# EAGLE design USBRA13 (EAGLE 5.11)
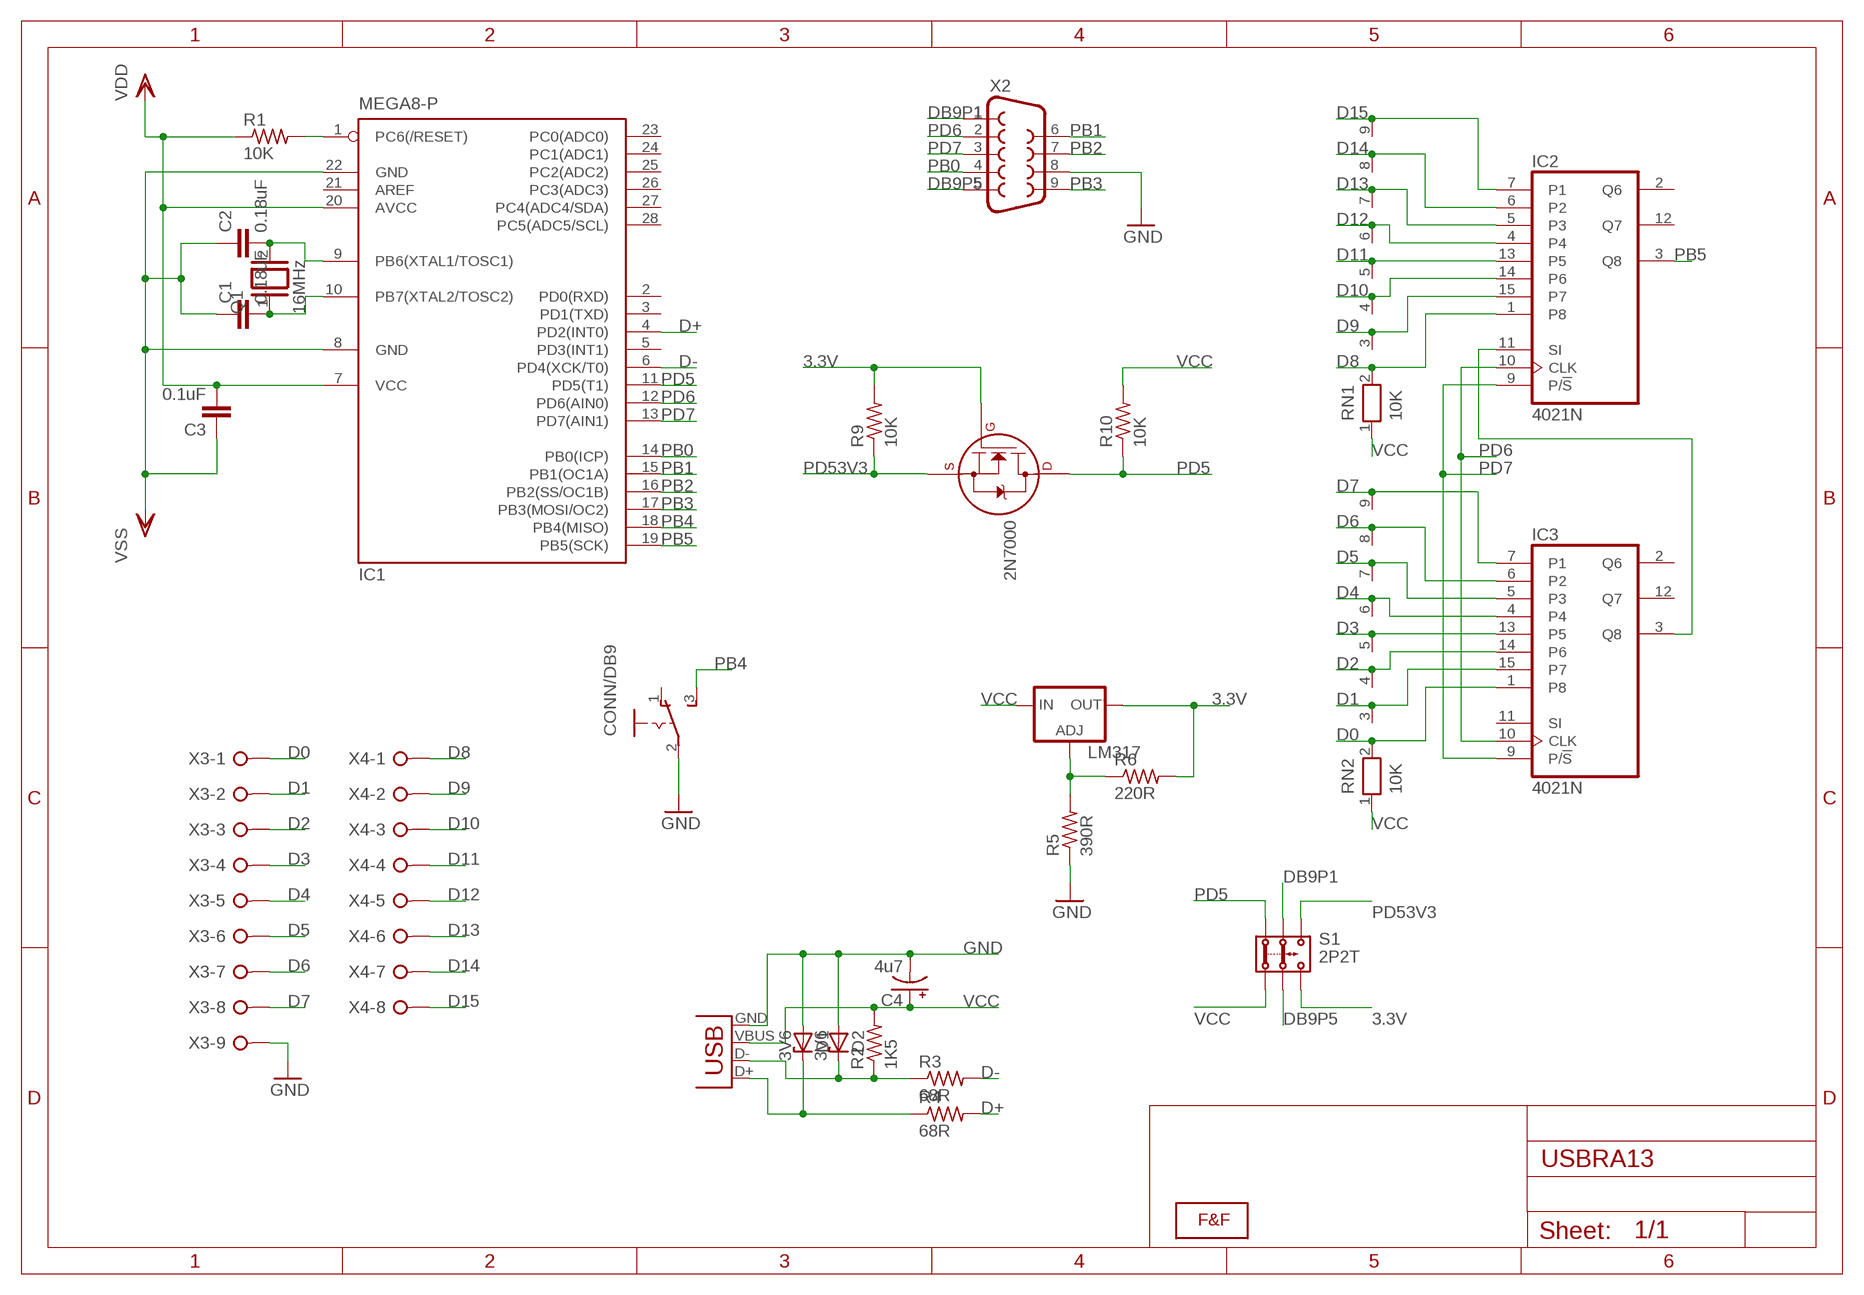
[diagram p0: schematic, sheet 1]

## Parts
2N7000  2N7000_TO92  [TO-92]
C1  0.18uF  C-EU050-024X044  [C050-024X044]
C2  0.18uF  C-EU050-024X044  [C050-024X044]
C3  0.1uF  C-EU050-024X044  [C050-024X044]
C4  4u7  CPOL-USE2.5-6  [E2,5-6]
CONN/DB9  CHAVE  [CHAVE]
D1  3V6  ZENER-DIODEZD-5  [ZDIO-5]
D2  3V6  ZENER-DIODEZD-5  [ZDIO-5]
IC1  MEGA8-P  [DIL28-3]
IC2  4021N  [DIL16]
IC3  4021N  [DIL16]
LM317  LM317TS  [317TS]
Q1  16MHz  XTAL/S  [QS]
R1  10K  R-US_0207/10  [0207/10]
R2  1K5  R-US_0207/10  [0207/10]
R3  68R  R-US_0207/10  [0207/10]
R4  68R  R-US_0207/10  [0207/10]
R5  390R  R-US_0207/10  [0207/10]
R6  220R  R-US_0207/10  [0207/10]
R9  10K  R-US_0207/10  [0207/10]
R10  10K  R-US_0207/10  [0207/10]
RN1  10K  RN08  [RN-9]
RN2  10K  RN08  [RN-9]
S1  2P2T  [2P2T]
U$1  LOGOLOGO_WITHOUT_SMOKE_BIG  [LOGO2_BIG]
X1  USBPTH  [USB-B-PTH]
X2  DB9MALE  [DB9_MALE]
X3  W237-09P  [W237-9P]
X4  W237-08P  [W237-8P]

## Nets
3.3V: 2N7000.2(G) LM317.2(OUT) R6.2 R9.2 S1.3.2
D0: IC3.1(P8) RN2.2 X3.1
D1: IC3.15(P7) RN2.3 X3.2
D2: IC3.14(P6) RN2.4 X3.3
D3: IC3.13(P5) RN2.5 X3.4
D4: IC3.4 RN2.6 X3.5
D5: IC3.5(P3) RN2.7 X3.6
D6: IC3.6(P2) RN2.8 X3.7
D7: IC3.7(P1) RN2.9 X3.8
D8: IC2.1(P8) RN1.2 X4.1
D9: IC2.15(P7) RN1.3 X4.2
D10: IC2.14(P6) RN1.4 X4.3
D11: IC2.13(P5) RN1.5 X4.4
D12: IC2.4 RN1.6 X4.5
D13: IC2.5(P3) RN1.7 X4.6
D14: IC2.6(P2) RN1.8 X4.7
D15: IC2.7(P1) RN1.9 X4.8
D+: IC1.4(PD2(INT0)) R4.2
D-: IC1.6(PD4(XCK/T0)) R3.2
DB9P1: S1.2.1 X2.1
DB9P5: S1.2.2 X2.5
GND: C1.1 C2.1 C3.1 C4.- CONN/DB9.2(P) D1.A D2.A IC1.8(GND) IC1.22(GND) R5.1 X1.GND X2.8 X3.9 ; supply symbol labelled VSS
N$1: IC1.1(PC6(/RESET)) R1.2
N$2: C2.2 IC1.9(PB6(XTAL1/TOSC1)) Q1.2
N$3: C1.2 IC1.10(PB7(XTAL2/TOSC2)) Q1.1
N$4: IC2.11(SI) IC3.3(Q8)
N$5: LM317.1(ADJ) R5.2 R6.1
N$8: D1.C R4.1 X1.D+
N$9: D2.C R2.1 R3.1 X1.D-
PB0: IC1.14(PB0(ICP)) X2.4
PB1: IC1.15(PB1(OC1A)) X2.6
PB2: IC1.16(PB2(SS/OC1B)) X2.7
PB3: IC1.17(PB3(MOSI/OC2)) X2.9
PB4: CONN/DB9.3(S) IC1.18(PB4(MISO))
PB5: IC1.19(PB5(SCK)) IC2.3(Q8)
PD5: 2N7000.3(D) IC1.11(PD5(T1)) R10.1 S1.1.1
PD6: IC1.12(PD6(AIN0)) IC2.10(CLK) IC3.10(CLK) X2.2
PD7: IC1.13(PD7(AIN1)) IC2.9(P/!S) IC3.9(P/!S) X2.3
PD53V3: 2N7000.1(S) R9.1 S1.3.1
VCC: C3.2 C4.+ IC1.7(VCC) IC1.20(AVCC) LM317.3(IN) R1.1 R2.2 R10.2 RN1.1 RN2.1 S1.1.2 X1.VBUS ; supply symbol labelled VDD
Unconnected: CONN/DB9.1(O) IC1.2(PD0(RXD)) IC1.3(PD1(TXD)) IC1.5(PD3(INT1)) IC1.21(AREF) IC1.23(PC0(ADC0)) IC1.24(PC1(ADC1)) IC1.25(PC2(ADC2)) IC1.26(PC3(ADC3)) IC1.27(PC4(ADC4/SDA)) IC1.28(PC5(ADC5/SCL)) IC2.2(Q6) IC2.12(Q7) IC3.2(Q6) IC3.11(SI) IC3.12(Q7)

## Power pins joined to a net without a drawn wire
GND: IC2.8(VSS) IC3.8(VSS)
VCC: IC2.16(VDD) IC3.16(VDD)

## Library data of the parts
2N7000 = transistors:2N700*: 2N7000, 2N7002, NDS7002A N-channel enhancement mode MOSFET
C1-C3 = rcl:C-EU: CAPACITOR, European symbol
C4 = adafruit:CPOL-US: POLARIZED CAPACITOR, American symbol
CONN/DB9 = switch-fef:CHAVE: chave Verificar
D1 D2 = diode:ZENER-DIODE: Z-Diode
IC1 = atmel:MEGA8-P: MICROCONTROLLER 8 Kbytes FLASH, 1 kbytes SRAM, 512 bytes EEPROM, USART, 4-channel 10 bit ADC, 2-channel 8 bit ADC Pin compatible with Atmega48, ATMega88, ATMega168 Source: avr.lbr; OC_FARNELL: unknown; OC_NEWARK: unknown
IC2 IC3 = 40xx:4021: 8-bit static SHIFT REGISTER
LM317 = v-reg:LM317TS: VOLTAGE REGULATOR
Q1 = special:XTAL/S: CRYSTAL
R1-R6 R9 R10 = adafruit:R-US_: RESISTOR, American symbol
RN1 RN2 = resistor-net:RN08: RESISTOR NETWORK; OC_FARNELL: unknown; OC_NEWARK: unknown
S1 = Itead_BP_110825:2P2T: BAS011
U$1 = F&F:LOGO: Faísca e Fumaça Logo
X1 = SparkFun:USB: USB Connectors USB-B-PTH is fully proven SKU : PRT-00139 USB-miniB is fully proven SKU : PRT-00587 USB-A-PCB is untested. USB-A-H is throughly reviewed, but untested. Spark Fun Electronics SKU : PRT-00437 USB-B-SMT is throughly reviewed, but untested. Needs silkscreen touching up. USB-A-S has not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
X2 = SparkFun:DB9: DB9 Connector Standard DB9 (D-Sub 9) serial connector. Can be used for CAN bus as well as RS485 and RS232. Footprint production proven. Spark Fun Electronics SKU : PRT-00429
X3 = con-wago-508:W237-09P: WAGO SREW CLAMP; OC_FARNELL: unknown; OC_NEWARK: unknown
X4 = con-wago-508:W237-08P: WAGO SREW CLAMP; OC_FARNELL: unknown; OC_NEWARK: unknown

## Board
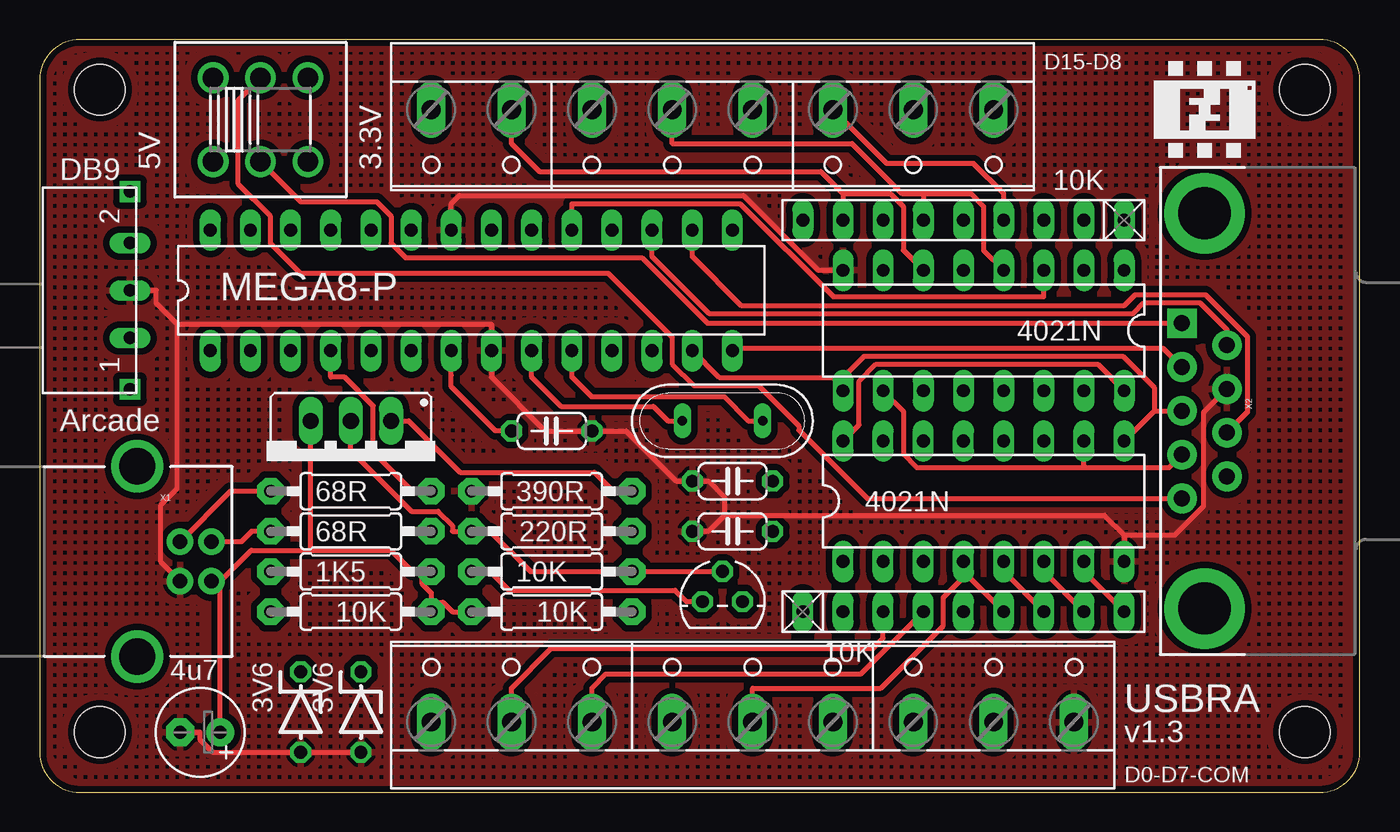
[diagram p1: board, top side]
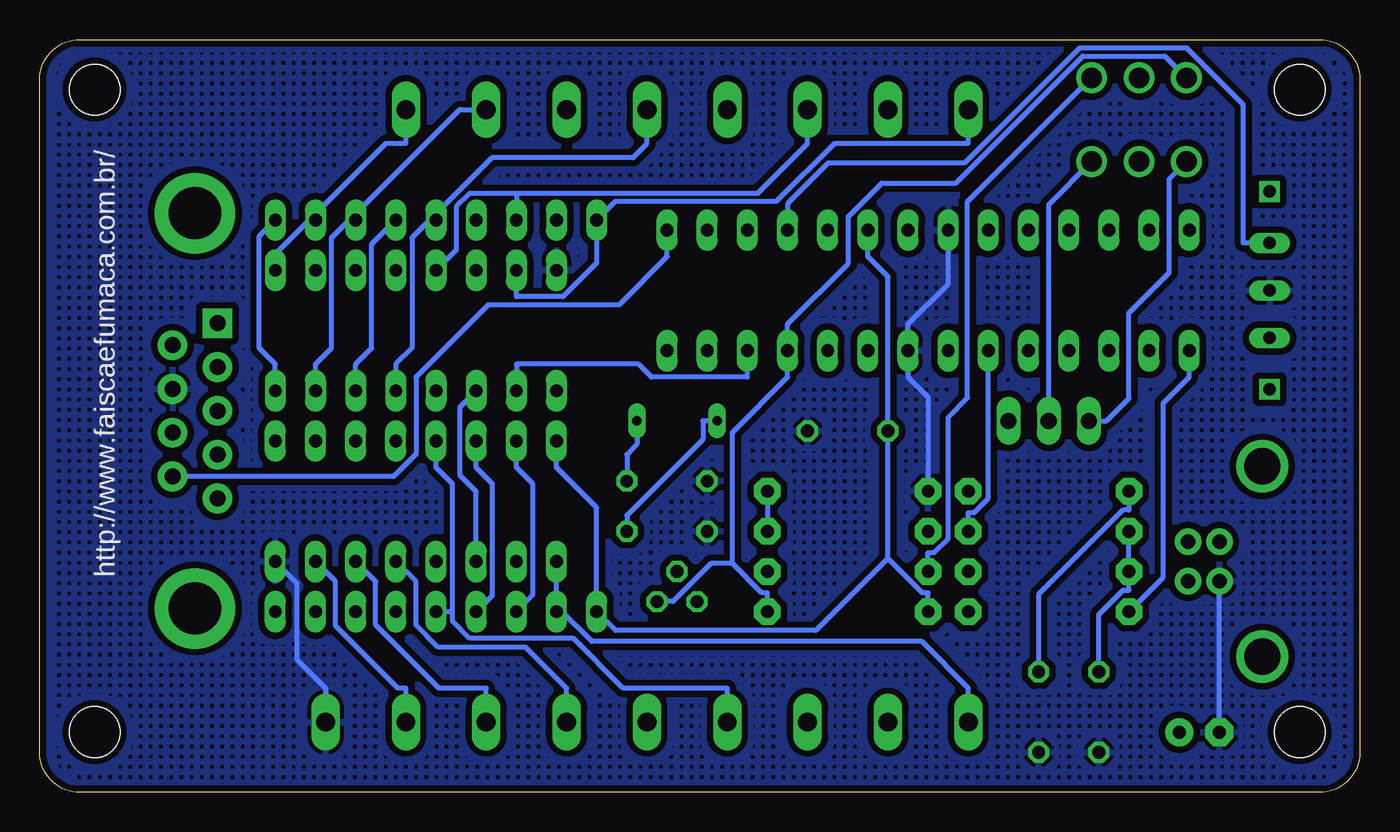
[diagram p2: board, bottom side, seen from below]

Size 83.49 x 47.62 mm. Coordinates in mm from the lower left corner, seen from the top.
Outline: 83.49,45.08 arc90 80.95,47.62 2.54,47.62 arc90 0,45.08 0,2.54 arc90 2.54,0 80.95,0 arc90 83.49,2.54 83.49,45.08
Copper layers (1*16): Top 0.035mm / dielectric 1.5mm / Bottom 0.035mm
Design rules "ITead_rule": minimum track width 6mil, minimum drill 12mil, track to track 6mil, track to pad 6mil, pad to pad 6mil, via to via 6mil, smd to smd 0mil, copper to edge 10mil, drill to drill 10mil, minimum pad ring 10mil, minimum via ring 6mil, stop-mask expansion 2mil, vias tented up to drill 100mil, thermal gap 10mil
Holes 3.2 mm at 3.81,44.45 3.81,3.81 80.01,44.45 80.01,3.81

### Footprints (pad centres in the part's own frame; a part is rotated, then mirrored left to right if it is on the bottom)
TO-92 = drill 0.813 octagon: 1 -1.27,0; 2 0,1.905; 3 1.27,0
C050-024X044 = drill 0.813 octagon: 1 -2.54,0; 2 2.54,0
E2,5-6 = drill 0.813 pad 1.778 round: + -1.27,0 | drill 0.813 pad 1.778 octagon: - 1.27,0
CHAVE = drill 0.8 long: 1 -3,0; 2 0,0; 3 3,0 | drill 0.8 square: P$1 -6.25,0; P$2 6.25,0
ZDIO-5 = drill 0.813 octagon: A 2.54,0; C -2.54,0
DIL28-3 = drill 0.813 long: 1 -16.51,-3.81; 2 -13.97,-3.81; 3 -11.43,-3.81; 4 -8.89,-3.81; 5 -6.35,-3.81; 6 -3.81,-3.81; 7 -1.27,-3.81; 8 1.27,-3.81; 9 3.81,-3.81; 10 6.35,-3.81; 11 8.89,-3.81; 12 11.43,-3.81; 13 13.97,-3.81; 14 16.51,-3.81; 15 16.51,3.81; 16 13.97,3.81; 17 11.43,3.81; 18 8.89,3.81; 19 6.35,3.81; 20 3.81,3.81; 21 1.27,3.81; 22 -1.27,3.81; 23 -3.81,3.81; 24 -6.35,3.81; 25 -8.89,3.81; 26 -11.43,3.81; 27 -13.97,3.81; 28 -16.51,3.81
DIL16 = drill 0.813 long: 1 -8.89,-3.81; 2 -6.35,-3.81; 3 -3.81,-3.81; 4 -1.27,-3.81; 5 1.27,-3.81; 6 3.81,-3.81; 7 6.35,-3.81; 8 8.89,-3.81; 9 8.89,3.81; 10 6.35,3.81; 11 3.81,3.81; 12 1.27,3.81; 13 -1.27,3.81; 14 -3.81,3.81; 15 -6.35,3.81; 16 -8.89,3.81
317TS = drill 1.016 long: 1 -2.54,-2.54; 2 0,-2.54; 3 2.54,-2.54
QS = drill 0.61 long: 1 -2.54,0; 2 2.54,0
0207/10 = drill 0.813 pad 1.676 octagon: 1 -5.08,0; 2 5.08,0
RN-9 = drill 0.813 long: 1 -10.16,0; 2 -7.62,0; 3 -5.08,0; 4 -2.54,0; 5 0,0; 6 2.54,0; 7 5.08,0; 8 7.62,0; 9 10.16,0
2P2T = drill 1.3 pad 1.93 round: 1.1 -3,2.65; 1.2 -3,-2.65; 2.1 0,2.65; 2.2 0,-2.65; 3.1 3,2.65; 3.2 3,-2.65
USB-B-PTH = drill 0.914 pad 1.676 round: D+ 0,1.25; D- 1.981,1.25; GND 0,-1.25; VBUS 1.981,-1.25 | drill 2.286 round: S1 -2.718,-6.02; S2 -2.718,6.02
DB9_MALE = drill 1.016 pad 1.88 round: 1 5.54,-1.42; 2 2.77,-1.42; 3 0,-1.42; 4 -2.77,-1.42; 6 4.15,1.42; 7 1.38,1.42; 8 -1.38,1.42; 9 -4.15,1.42 | drill 1.016 pad 1.88 square: 5 -5.54,-1.42 | drill 3.302 pad 5.08 round: G1 -12.5,0; G2 12.5,0
W237-9P = drill 1.194 long: 1 -20.32,-0.635; 2 -15.24,-0.635; 3 -10.16,-0.635; 4 -5.08,-0.635; 5 0,-0.635; 6 5.08,-0.635; 7 10.16,-0.635; 8 15.24,-0.635; 9 20.32,-0.635
W237-8P = drill 1.194 long: 1 -17.78,-0.635; 2 -12.7,-0.635; 3 -7.62,-0.635; 4 -2.54,-0.635; 5 2.54,-0.635; 6 7.62,-0.635; 7 12.7,-0.635; 8 17.78,-0.635

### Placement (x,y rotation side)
2N7000  43.18,12.06 0 top
C1  43.81,19.68 0 top
C2  43.81,16.51 0 top
C3  32.38,22.86 180 top
C4  10.16,3.81 180 top
CONN/DB9  5.71,31.75 90 top
D1  20.32,5.08 270 top
D2  16.51,5.08 270 top
IC1  27.3,31.75 0 top
IC2  59.69,29.21 180 top
IC3  59.69,18.41 0 top
LM317  19.68,20.95 180 top
Q1  43.18,23.5 180 top
R1  19.68,11.43 180 top
R2  19.68,13.97 0 top
R3  19.68,16.51 0 top
R4  19.68,19.05 0 top
R5  32.38,19.05 0 top
R6  32.38,16.51 180 top
R9  32.38,13.97 0 top
R10  32.38,11.43 180 top
RN1  58.42,36.2 180 top
RN2  58.42,11.43 0 top
S1  13.97,42.55 0 top
U$1  73.66,43.18 0 top
X1  8.89,14.61 0 top
X2  73.66,24.13 270 top
X3  45.09,5.08 0 top
X4  42.55,42.55 180 top

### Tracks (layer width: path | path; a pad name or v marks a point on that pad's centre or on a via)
3.3V
  Top 0.305: 2N7000.2 42.16,13.97 R9.2 31.04,13.97 28.5,16.51 R6.2 26.11,16.51 26.11,16.88 25.21,17.78 23.52,17.78 19.68,21.61 LM317.2
  Bottom 0.305: S1.3.2 19.68,37.18 LM317.2
D0
  Bottom 0.305: X3.1 24.77,6.59 27.71,9.54 48.56,9.54 50.45,11.43 RN2.2 IC3.1
D1
  Top 0.305: RN2.3 53.34,9.75 52.68,9.1 32.35,9.1 29.84,6.59 X3.2
  Bottom 0.305: IC3.15 53.34,20.55 52.29,19.5 52.29,12.48 RN2.3
D2
  Top 0.305: RN2.4 51.94,7.49 35.82,7.49 34.92,6.59 X3.3
  Bottom 0.305: IC3.14 55.88,20.55 54.85,19.52 54.85,12.46 RN2.4
D3
  Bottom 0.305: 57.39,11.43 57.39,10.84 56.3,9.75 49.74,9.75 46.58,6.59 40.01,6.59 X3.4 | 57.39,11.43 57.39,19.52 58.42,20.55 IC3.13 | 57.39,11.43 RN2.5
D4
  Top 0.305: 58.61,13.78 58.42,13.97 IC3.4 | 58.61,13.78 RN2.6 | 58.61,13.78 57.15,12.32 57.15,10.55 53.2,6.59 45.09,6.59 X3.5
D5
  Top 0.305: RN2.7 60.96,13.97 IC3.5
  Bottom 0.305: X3.6 50.16,6.59 52.75,9.18 58.28,9.18 59.69,10.59 59.69,13.34 IC3.5
D6
  Top 0.305: RN2.8 63.5,13.97 IC3.6
  Bottom 0.305: X3.7 55.24,6.59 58.23,6.59 62.23,10.59 62.23,13.34 IC3.6
D7
  Top 0.305: RN2.9 66.04,13.97 IC3.7
  Bottom 0.305: X3.8 60.33,6.59 60.82,6.59 64.77,10.54 64.77,13.34 IC3.7
D8
  Bottom 0.305: X4.1 60.33,41.03 61.6,41.03 66.04,36.6 | 66.04,36.6 68.58,34.06 IC2.1 | 66.04,36.6 RN1.2
D9
  Bottom 0.305: X4.2 56.93,43.18 63.5,36.61 | IC2.15 66.04,27.08 65.02,28.09 65.02,35.08 63.5,36.61 | 63.5,36.61 RN1.3
D10
  Top 0.305: X4.3 53.57,39.77 59.06,39.77 60.96,37.87 RN1.4
  Bottom 0.305: IC2.14 63.5,27.08 62.48,28.09 62.48,34.67 RN1.4
D11
  Bottom 0.305: X4.4 45.09,41.03 45.98,40.14 54.88,40.14 58.42,36.6 | IC2.13 60.96,27.08 59.94,28.09 59.94,35.07 58.42,36.6 | 58.42,36.6 RN1.5
D12
  Top 0.305: 55.88,37.87 54.54,37.87 51.38,41.03 40.01,41.03 X4.5 | IC2.4 59.69,34.29 59.69,37.06 58.88,37.87 55.88,37.87 | 55.88,37.87 RN1.6
D13
  Bottom 0.305: 53.34,37.87 56.31,37.87 57.15,37.03 57.15,34.29 IC2.5 | 53.34,37.87 38.09,37.87 34.92,41.03 X4.6 | 53.34,37.87 RN1.7
D14
  Top 0.305: 50.8,37.87 49.4,39.27 31.61,39.27 29.84,41.03 X4.7 | 50.8,37.87 53.79,37.87 54.61,37.05 54.61,34.29 IC2.6 | 50.8,37.87 50.8,37.74 RN1.8
D15
  Bottom 0.305: X4.8 24.77,41.03 33.24,41.03 36.91,37.36 47.09,37.36 RN1.9 48.26,33.46 50.38,31.34 53.34,31.34 IC2.7
D+
  Top 0.305: IC1.4 18.41,26.26 19.28,26.26 21.11,24.44 21.11,21.51 23.57,19.05 R4.2
D-
  Bottom 0.305: R3.2 24.77,17.7 24.39,17.7 23.5,18.6 IC1.6
DB9P1
  Top 0.305: X2.1 52.34,18.59 48.02,22.91 48.02,23.16 45.46,25.72 41.39,25.72 40.01,27.1 40.01,28.79 35.96,32.84 16.49,32.84 14.61,34.72 14.61,36.44 12.56,38.48 12.56,43.79 S1.2.1
DB9P5
  Top 0.305: X2.5 42.23,29.67 38.08,33.82 23.14,33.82 22.23,34.73 22.23,36.45 21.33,37.35 16.51,37.35 S1.2.2
GND
  Top 0.305: 8.7,29.62 8.7,19.21 7.67,18.17 7.67,14.58 X1.GND | 8.7,29.62 7.38,30.94 7.38,31.75 CONN/DB9.2 | 8.7,29.62 28.57,29.62 IC1.8 28.57,26.26 31.98,22.86 C3.1 37.08,22.86 40.26,19.68 C1.1 42.29,19.68 43.31,18.67 43.31,17.53 | IC2.8 49.23,33.02 44.5,37.74 26.54,37.74 26.04,37.24 IC1.22 | 43.31,17.53 42.29,16.51 C2.1 | 68.58,16.28 67.33,17.53 43.31,17.53 | 68.58,16.28 68.58,16.15 IC3.8 | 68.58,16.28 71.79,16.28 73.62,18.11 73.62,24.05 X2.8 | C4.- 10.13,3.81 10.13,3.34 10.94,2.54 D2.A D1.A
  Bottom 0.305: C4.- X1.GND | IC3.8 67.23,13.26 67.23,8.42 65.41,6.59 X3.9 | IC1.22 26.04,32.16 28.57,29.62 IC1.8 28.57,26.26 27.3,24.99 R5.1
  pour Bottom (isolate 0.406, hatched): 0,46.99 83.82,46.99 83.82,0 0,0
  pour Top (isolate 0.406, hatched): 0,46.99 83.82,46.99 83.82,0 0,0
N$1
  Bottom 0.305: IC1.1 10.79,26.26 12.44,24.62 12.44,13.6 R1.2
N$2
  Top 0.305: Q1.2 39.73,23.5 38.81,24.41 32.97,24.41 31.11,26.26 IC1.9
  Bottom 0.305: C2.2 46.35,17.53 41.55,22.33 41.55,23.5 Q1.2
N$3
  Top 0.305: IC1.10 33.66,26.26 34.9,25.02 43.28,25.02 44.81,23.5 Q1.1
  Bottom 0.305: Q1.1 45.72,22.02 46.35,21.39 C1.2
N$4
  Bottom 0.305: IC3.3 55.88,19.02 56.91,20.06 56.91,24.37 IC2.11
N$5
  Top 0.305: LM317.1 23.34,23.5 26.59,20.24 35.08,20.24 36.27,19.05 R5.2
  Bottom 0.305: R5.2 R6.1
N$8
  Top 0.305: X1.D+ 12.09,19.05 R4.1
  Bottom 0.305: R4.1 14.61,17.86 14.98,17.86 20.32,12.51 D1.C
N$9
  Top 0.305: R3.1 13.41,16.51 12.76,15.86 X1.D-
  Bottom 0.305: D2.C 16.51,11.24 14.98,12.78 14.61,12.78 R2.1 R3.1
PB0
  Top 0.305: X2.4 71.04,28.1 43.98,28.1 IC1.14
PB1
  Bottom 0.305: IC1.15 43.81,33.88 46.86,30.84 55.13,30.84 59.69,26.28 59.69,21.39 61.1,19.98 X2.6
PB2
  Top 0.305: X2.7 76.38,24.05 76.38,28.82 73.72,31.48 69.27,31.48 68.59,30.8 44.36,30.8 41.27,33.88 IC1.16
PB3
  Top 0.305: IC1.17 38.73,33.88 42.33,30.29 69.16,30.29 69.84,30.97 73.38,30.97 75.08,29.26 X2.9
PB4
  Bottom 0.305: CONN/DB9.3 7.38,34.75 7.38,43.5 10.96,47.07 17.74,47.07 25,39.81 33.62,39.81 36.2,37.24 IC1.18
PB5
  Top 0.305: IC1.19 33.66,37.24 44.29,37.24 50.19,31.34 63.5,31.34 IC2.3
PD5
  Bottom 0.305: 39.68,14.47 37.84,12.62 37.47,12.62 R10.1 | 39.68,14.47 39.68,22.78 36.2,26.26 IC1.11 36.2,29.62 32.35,33.46 32.35,36.42 30.24,38.54 25.55,38.54 17.53,46.56 12.34,46.56 S1.1.1 | 39.68,14.47 41.03,14.47 43.43,12.06 2N7000.3
PD6
  Top 0.305: 66.04,20.55 55.45,20.55 54.61,21.39 54.61,24.13 IC2.10 | 66.04,20.55 66.04,20.68 IC3.10 | X2.2 71.43,20.55 66.04,20.55
  Bottom 0.305: IC1.12 38.73,26.26 44.81,26.26 45.62,27.08 53.34,27.08 IC2.10
PD7
  Top 0.305: 50.8,26.24 52.15,27.59 68.49,27.59 70.48,25.59 70.48,24.13 | 70.48,24.13 IC3.9 | 70.48,24.13 X2.3 | 50.8,26.24 42.97,26.24 IC1.13 | 50.8,26.24 IC2.9
PD53V3
  Top 0.305: 2N7000.1 40.89,12.06 40.18,12.78 29.69,12.78 28.5,13.97 R9.1
  Bottom 0.305: R9.1 27.3,15.16 26.93,15.16 26.04,16.06 26.04,23.72 24.81,24.95 24.81,37.36 S1.3.1
VCC
  Top 0.305: R10.2 26.11,11.43 25.51,12.03 24.77,12.03 | 24.77,12.03 24.77,12.62 24.17,13.22 24.17,13.97 | 24.77,12.03 R1.1 | 17.14,15.32 LM317.3 | 17.14,15.32 22.23,15.32 23.57,13.97 24.17,13.97 | 11.43,13.36 13.39,15.32 17.14,15.32 | 24.17,13.97 R2.2 | 11.43,13.36 X1.VBUS | C4.+ 11.43,13.36 | IC3.16 51.82,23.24 51.82,26 52.9,27.08 66.9,27.08 IC2.16 | IC1.7 26.04,26.39 26.04,25.65 28.83,22.86 C3.2
  Bottom 0.305: 29.84,14.79 34.4,10.23 47.06,10.23 RN2.1 48.26,18.01 50.8,20.55 IC3.16 | 29.84,14.79 C3.2 29.84,32.61 31.11,33.88 IC1.20 | 29.84,14.79 27.68,12.62 27.3,12.62 R10.2 | LM317.3 16.03,23.5 14.61,24.92 14.61,30.32 12.06,32.86 12.06,38.8 S1.1.2 | IC2.16 68.58,27.08 69.6,28.09 69.6,35.18 RN1.1

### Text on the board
tPlace: D15-D8 | DB9 | 5V | 3.3V | Arcade | USBRA | v1.3 | D0-D7-COM
bPlace: http://www.faiscaefumaca.com.br/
